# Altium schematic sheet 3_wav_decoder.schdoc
size 309 x 223 mm; Symbol: Sheet-Symbol_A4; Device: Sheet-Symbol_A4; Company: 嘉立创EDA; Version: V1.0; Page Size: A4; @Project Name: fm33; @Page Count: 3; @Update Date: 2025-07-19; @Create Date: 2025-07-15; @Schematic Name: Schematic6; @Page No: 3; @Page Name: wav_decoder; Title Block Position: 3; Width: 1170; Height: 825; Region Start: 1; X Region Count: 6; Y Region Count: 4; Blade Width: 10; @Board Name: core_3; @Create Time: 13:11:25; @Update Time: 10:45:30
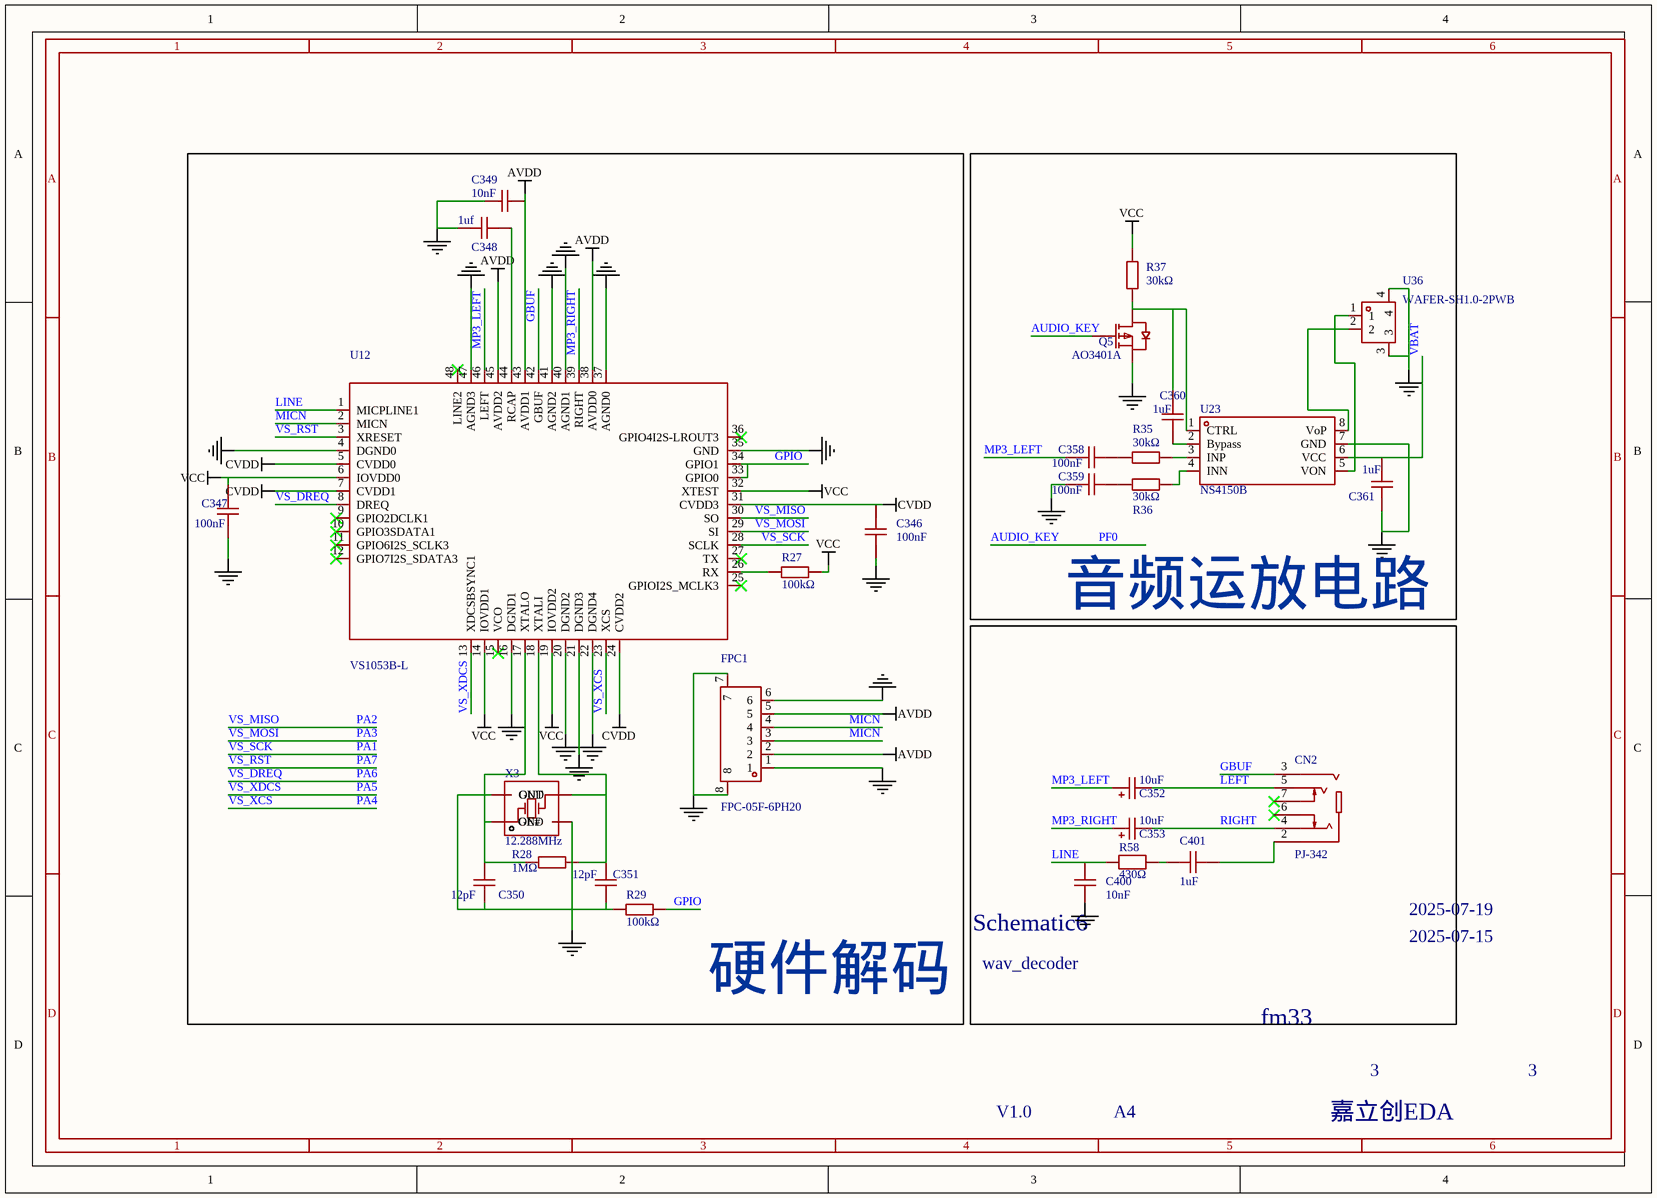
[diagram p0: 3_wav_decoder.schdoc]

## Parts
C346  100nF  [C0402-NSK]
C347  100nF  [C0402-NSK]
C348  1uf  [C0402-NSK]
C349  10nF  [C0402-NSK]  (value not drawn)
C350  12pF  [C0402-NSK]  (value not drawn)
C351  12pF  [C0402-NSK]  (value not drawn)
C352  10uF  [CAP-SMD_L3.2-W1.6-RD-C7171]  (value not drawn)
C353  10uF  [CAP-SMD_L3.2-W1.6-RD-C7171]  (value not drawn)
C358  100nF  [C0402-NSK]  (value not drawn)
C359  100nF  [C0402-NSK]  (value not drawn)
C360  1uF  [C0402-NSK]  (value not drawn)
C361  1uF  [C0402-NSK]  (value not drawn)
C400  10nF  [C0402-NSK]  (value not drawn)
C401  1uF  [C0402-NSK]  (value not drawn)
CN2  PJ-342  [AUDIO-SMD_PJ-342]  (value not drawn)
FPC1  FPC-05F-6PH20  [FPC-SMD_6P-P0.50_XUNPU_FPC-05F-6PH20]  (value not drawn)
Q5  AO3401A  [SOT-23_L2.9-W1.3-P1.90-LS2.4-BR]  (value not drawn)
R27  100kΩ  [R0402]  (value not drawn)
R28  1MΩ  [R0402]  (value not drawn)
R29  100kΩ  [R0402]  (value not drawn)
R35  30kΩ  [R0402]  (value not drawn)
R36  30kΩ  [R0402]  (value not drawn)
R37  30kΩ  [R0402]  (value not drawn)
R58  430Ω  [R0402]  (value not drawn)
U12  VS1053B-L  [LQFP-48_L7.0-W7.0-P0.50-LS9.0-BL]  (value not drawn)
U23  NS4150B  [MSOP-8_L3.0-W3.0-P0.65-LS5.0-BL]  (value not drawn)
U36  WAFER-SH1.0-2PWB  [CONN-SMD_2P-P1.00_XUNPU_WAFER-SH1.0-2PWB]  (value not drawn)
X3  12.288MHz  [CRYSTAL-SMD_4P-L3.2-W2.5-BL-2]  (value not drawn)

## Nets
AVDD: C349.1 FPC1.2 FPC1.5 U12.38(AVDD0) U12.43(AVDD1) U12.45(AVDD2)
CVDD: C346.2 U12.5(CVDD0) U12.7(CVDD1) U12.24(CVDD2) U12.31(CVDD3)
GND: C346.1 C347.1 C348.2 C349.2 C350.1 C351.1 C359.1 C361.1 C400.1 FPC1.1 FPC1.6 FPC1.7 FPC1.8 Q5.2(S) R29.1 U12.4(DGND0) U12.16(DGND1) U12.20(DGND2) U12.21(DGND3) U12.22(DGND4) U12.35(GND) U12.37(AGND0) U12.40(AGND1) U12.41(AGND2) U12.47(AGND3) U23.7(GND) U36.3 U36.4 X3.2(GND) X3.4(GND)
VCC: C347.2 R27.2 R37.2 U12.6(IOVDD0) U12.14(IOVDD1) U12.19(IOVDD2) U12.32(XTEST)
AUDIO_KEY: Q5.1(G)  [also labelled PF0]
GBUF: CN2.3 U12.42(GBUF)
GPIO: R29.2 U12.33(GPIO0) U12.34(GPIO1)
LEFT: C352.2 CN2.5
LINE: C400.2 R58.1 U12.1(MICPLINE1)
MICN: FPC1.3 FPC1.4 U12.2(MICN)
MP3_LEFT: C352.1 C358.1 U12.46(LEFT)
MP3_RIGHT: C353.1 U12.39(RIGHT)
PA1: U12.28(SCLK)  [also labelled VS_SCK]
PA2: U12.30(SO)  [also labelled VS_MISO]
PA3: U12.29(SI)  [also labelled VS_MOSI]
PA4: U12.23(XCS)  [also labelled VS_XCS]
PA5: U12.13(XDCSBSYNC1)  [also labelled VS_XDCS]
PA6: U12.8(DREQ)  [also labelled VS_DREQ]
PA7: U12.3(XRESET)  [also labelled VS_RST]
RIGHT: C353.2 CN2.4
VBAT: C361.2 U23.6(VCC)
NetC348_1: C348.1 U12.44(RCAP)
NetC350_2: C350.2 R28.1 U12.17(XTALO) X3.1(OE#)
NetC351_2: C351.2 R28.2 U12.18(XTALI) X3.3(OUT)
NetC358_2: C358.2 R35.1
NetC359_2: C359.2 R36.1
NetC360_1: C360.1 U23.2(Bypass)
NetC360_2: C360.2 Q5.3(D) R37.1 U23.1(CTRL)
NetC401_1: C401.1 R58.2
NetC401_2: C401.2 CN2.2
NetR27_1: R27.1 U12.26(RX)
NetR35_2: R35.2 U23.3(INP)
NetR36_2: R36.2 U23.4(INN)
NetU23_5: U23.5(VON) U36.1
NetU23_8: U23.8(VoP) U36.2

Not connected (* = marked no-connect by the designer): CN2 6* 7*; U12 9(GPIO2DCLK1)* 10(GPIO3SDATA1)* 11(GPIO6I2S_SCLK3)* 12(GPIO7I2S_SDATA3)* 15(VCO)* 25(GPIOI2S_MCLK3)* 27(TX)* 36(GPIO4I2S-LROUT3)* 48(LINE2)*

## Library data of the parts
C346-C348 = CAP_0402: Symbol: CapAcitance; Convert to PCB: yes
C349 C400 = CL05B103KB5NNNC: 容值:10nF;精度:±10%;额定电压:50V;材质(温度系数):X7R;; Manufacturer: SAMSUNG(三星); Add into BOM: yes; Tolerance: ±10%; Voltage Rated: 50V; Temperature Coefficient: X7R
C350 C351 = GRM1555C1H120JA01D: 容值:12pF;精度:±5%;额定电压:50V;材质(温度系数):C0G;; Manufacturer: muRata(村田); Add into BOM: yes; Tolerance: ±5%; Voltage Rated: 50V; Temperature Coefficient: C0G
C352 C353 = TAJA106K016RNJ: 容值:10uF;精度:±10%;额定电压:16V;等效串联电阻(ESR):3Ω@100kHz;; Manufacturer: Kyocera AVX; Add into BOM: yes; Tolerance: ±10%; Voltage Rating: 16V
C358 C359 = CL05B104KB54PNC: 容值:100nF;精度:±10%;额定电压:50V;材质(温度系数):X7R;; Manufacturer: SAMSUNG(三星); Add into BOM: yes; Tolerance: ±10%; Voltage Rated: 50V; Temperature Coefficient: X7R
C360 C361 C401 = CL05A105KA5NQNC: 容值:1uF;精度:±10%;额定电压:25V;材质(温度系数):X5R;; Manufacturer: SAMSUNG(三星); Add into BOM: yes; Tolerance: ±10%; Voltage Rated: 25V; Temperature Coefficient: X5R
CN2 = PJ-342_C668606: 连接器类型:3.5mm耳机座;额定电流:500mA;额定电压:30V;触头材质:铜;触头镀层:金;工作温度范围:-30℃~+70℃;; Manufacturer: SHOU HAN(首韩); Add into BOM: yes; Current Rating (Max): 500mA; Voltage Rating (Max): 30V
FPC1 = FPC-05F-6PH20: 锁定特性:翻盖式;触点类型:下接;触点数量:6P;间距:0.5mm;安装类型:卧贴;工作温度范围:-25℃~+85℃;; Manufacturer: XUNPU(讯普); Add into BOM: yes; Locking Feature: 翻盖式; Number of Contacts: 6P; Pitch: 0.5mm; FFC, FCB Thickness: 0.3mm
Q5 = AO3401A_C15127: 类型:1个P沟道;漏源电压(Vdss):30V;连续漏极电流(Id):4A;导通电阻(RDS(on)@Vgs,Id):44mΩ@10V,4.3A;功率(Pd):1.4W;阈值电压(Vgs(th)@Id):1.3V@250uA;; Manufacturer: AOS; Add into BOM: yes; Type: 1个P沟道; Drain Source Voltage (Vdss): 30V; Continuous Drain Current (Id): 4A; Power Dissipation (Pd): 1.4W; Total Gate Charge (Qg@Vgs): 12.2nC@4.5V; Input Capacitance (Ciss@Vds): 1.2nF@15V
R27 R29 = 0402WGF1003TCE: 电阻类型:厚膜电阻;阻值:100kΩ;精度:±1%;功率:62.5mW;最大工作电压:50V;温度系数:±100ppm/℃;; Manufacturer: UNI-ROYAL(厚声); Add into BOM: yes; Tolerance: ±1%; Power(Watts): 62.5mW; Overload Voltage (Max): 50V
R28 = 0402WGF1004TCE: 电阻类型:厚膜电阻;阻值:1MΩ;精度:±1%;功率:62.5mW;最大工作电压:50V;温度系数:±100ppm/℃;; Manufacturer: UNI-ROYAL(厚声); Add into BOM: yes; Tolerance: ±1%; Power(Watts): 62.5mW; Overload Voltage (Max): 50V
R35-R37 = RC0402FR-0730KL: 电阻类型:厚膜电阻;阻值:30kΩ;精度:±1%;功率:62.5mW;最大工作电压:50V;温度系数:±100ppm/℃;; Manufacturer: YAGEO(国巨); Add into BOM: yes; Tolerance: ±1%; Power(Watts): 62.5mW; Overload Voltage (Max): 50V
R58 = ERA2AEB431X: 电阻类型:薄膜电阻;阻值:430Ω;精度:±0.1%;功率:63mW;温度系数:±25ppm/℃;; Manufacturer: PANASONIC(松下); Add into BOM: yes; Tolerance: ±0.1%; Power(Watts): 63mW
U12 = VS1053B-L: MP3芯片; Manufacturer: VLSI; Add into BOM: yes
U23 = NS4150B_C189961: 功放类型:D类功放;输出功率:3Wx1@4Ω;; Manufacturer: Nsiway(纳芯威); Symbol: NS4150; Add into BOM: yes; Type of Power Amplifier: D类功放; Supply Voltage: 3V~5.25V
U36 = WAFER-SH1.0-2PWB: 插针结构:1x2P;间距:1mm;安装方式:卧贴;参考系列:SH;总PIN数:2P;排数:1;每排PIN数:2;行距:-;额定电流:1A;触头材质:黄铜;触头镀层:-;工作温度:-25℃~+85℃;; Manufacturer: XUNPU(讯普); Add into BOM: yes; Pins Structure: 1x2P; Pitch: 1mm; Reference Series: SH; Number of PINs Per Row: 2; Current Rating: 1A; Voltage Rating: 50V; Plastic Material: LCP; Supplementary Features: 辅助焊脚; Z-Height of the Board: 3.15mm; X-Length of Bottom Edge on Board (Spacing Line): 4.35mm; Y-Width of Bottom Edge on Board: 5.05mm
X3 = TXM12.288M0004322FBCDO00T: 晶振类型:贴片晶振;频率:12.288MHz;常温频差:±10ppm;负载电容:12pF;频率稳定度:±20ppm;; Manufacturer: YJX(雅晶鑫); Symbol: SMD-3225_4P 12.288MHZ 12PF; Add into BOM: yes; Normal temperature Frequency Tolerance: ±10ppm; Load Capacitance: 12pF; Frequency Stability: ±20ppm; Equivalent Series Resistance(ESR): 60Ω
